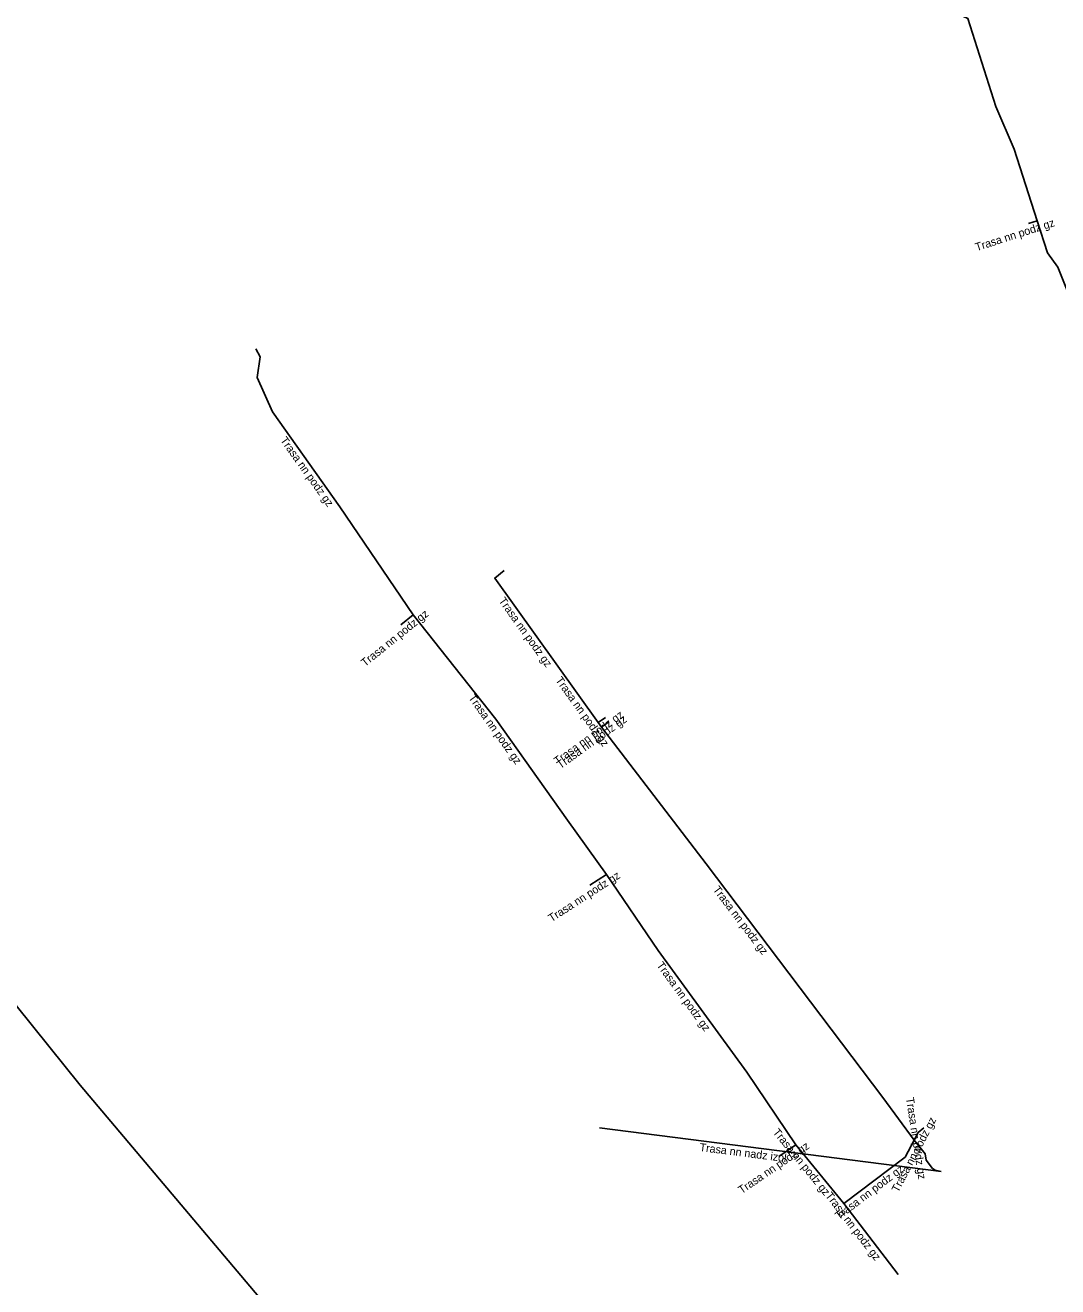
# Model space of a CAD drawing. Extents: x -660151 to -659156, y -1008082 to -1007440.
# Drawn here: x -660014.7 to -659950.2, y -1007835.1 to -1007756.3 of the extents above; entities that cross this region are included whole.
import ezdxf

# ---------------------------------------------------------------- set-up
doc = ezdxf.new("R2010")
doc.units = 0
for name, color, linetype in [('Popiskový text - Ostatní atributy Trasy', 7, 'Continuous'), ('Spojnice NN', 7, 'Continuous'), ('Spojnice VN', 7, 'Continuous')]:
    doc.layers.add(name, color=color, linetype=linetype)

msp = doc.modelspace()

# ---------------------------------------------------------------- linework, layer by layer
at = {"layer": 'Spojnice NN'}
for points in [[(-659951.49, -1007768.51), (-659952.93, -1007764.03), (-659954.06, -1007761.37), (-659955.82, -1007755.86), (-659956.44, -1007755.57), (-659956.81, -1007754.84), (-659957.87, -1007750.73), (-659957.89, -1007750.04), (-659960.3, -1007740.44), (-659960.22, -1007739.7), (-659960.9, -1007737.11)], [(-659951.49, -1007768.51), (-659952.02, -1007768.68)], [(-659944.43, -1007784.92), (-659944.79, -1007784.16), (-659947.9, -1007777.78), (-659947.74, -1007777.61), (-659949.74, -1007772.54), (-659950.2, -1007771.4), (-659950.85, -1007770.5), (-659951.49, -1007768.51)], [(-659990.46, -1007793.12), (-659995.04, -1007786.37), (-659999.26, -1007780.45), (-660000.21, -1007778.3), (-660000.03, -1007777), (-660000.29, -1007776.51)], [(-659978.91, -1007799.86), (-659985.37, -1007790.83), (-659984.78, -1007790.36)], [(-659990.46, -1007793.12), (-659991.24, -1007793.75)], [(-659978.38, -1007809.34), (-659980.82, -1007805.95), (-659985.3, -1007799.64), (-659990.46, -1007793.12)], [(-659978.91, -1007799.86), (-659978.46, -1007799.53)], [(-659978.71, -1007800.14), (-659978.91, -1007799.86)], [(-659978.71, -1007800.14), (-659978.25, -1007799.81)], [(-659959.17, -1007825.94), (-659961.12, -1007823.28), (-659972.17, -1007808.69), (-659978.71, -1007800.14)], [(-659978.38, -1007809.34), (-659979.43, -1007810.02)], [(-659966.56, -1007826.24), (-659969.63, -1007821.71), (-659975.16, -1007814.09), (-659978.38, -1007809.34)], [(-659978.835, -1007825.176), (-659957.49, -1007827.9)], [(-659959.17, -1007825.94), (-659958.93, -1007825.48), (-659958.56, -1007825.18)], [(-659963.56, -1007829.9), (-659959.74, -1007827.01), (-659959.17, -1007825.94)], [(-659959.17, -1007825.94), (-659958.49, -1007826.81), (-659958.43, -1007827.2), (-659958.03, -1007827.71), (-659957.85, -1007827.83), (-659957.49, -1007827.9)], [(-659966.56, -1007826.24), (-659967.62, -1007826.96)], [(-659963.56, -1007829.9), (-659966.56, -1007826.24)], [(-659960.16, -1007834.34), (-659963.56, -1007829.9)]]:
    msp.add_lwpolyline(points, dxfattribs=at)
at = {"layer": 'Spojnice VN'}
msp.add_lwpolyline([(-660145.05, -1007664.954), (-660077.733, -1007742.803), (-660055.375, -1007768.742), (-660028.126, -1007801.531), (-660011.262, -1007822.512), (-659996.272, -1007840.288), (-659970.295, -1007871.191), (-659939.672, -1007907.781), (-659898.47, -1007958.965), (-659880.172, -1007980.335), (-659865.432, -1007960.268), (-659851.63, -1007943.04)], dxfattribs=at)

# ---------------------------------------------------------------- texts
at = {"layer": 'Popiskový text - Ostatní atributy Trasy'}
for s, rotation, p in [('Trasa nn podz gz', 17.78389, (-659955.264, -1007770.403)), ('Trasa nn podz gz', 305.48271, (-659998.796, -1007782.221)), ('Trasa nn podz gz', 305.57967, (-659985.154, -1007792.25)), ('Trasa nn podz gz', 38.92754, (-659993.471, -1007796.387)), ('Trasa nn podz gz', 305.53768, (-659981.602, -1007797.209)), ('Trasa nn podz gz', 305.37415, (-659987.042, -1007798.31)), ('Trasa nn podz gz', 36.25384, (-659981.44, -1007802.522)), ('Trasa nn podz gz', 35.65533, (-659981.265, -1007802.773)), ('Trasa nn podz gz', 32.92786, (-659981.82, -1007812.342)), ('Trasa nn podz gz', 307.13913, (-659971.768, -1007810.298)), ('Trasa nn podz gz', 305.96921, (-659975.286, -1007815.023)), ('Trasa nn podz gz', 278.74616, (-659959.685, -1007823.319)), ('Trasa nn podz gz', 62.44719, (-659960.164, -1007829.252)), ('Trasa nn podz gz', 309.34052, (-659968.031, -1007825.471)), ('Trasa nn podz gz', 34.18612, (-659969.945, -1007829.326)), ('Trasa nn nadz izol', 352.72736, (-659972.599, -1007826.627)), ('Trasa nn podz gz', 37.10913, (-659963.879, -1007830.957)), ('Trasa nn podz gz', 307.44366, (-659964.744, -1007829.424))]:
    msp.add_text(s, height=0.5, rotation=rotation, dxfattribs=at).set_placement(p)

doc.saveas('drawing.dxf')
